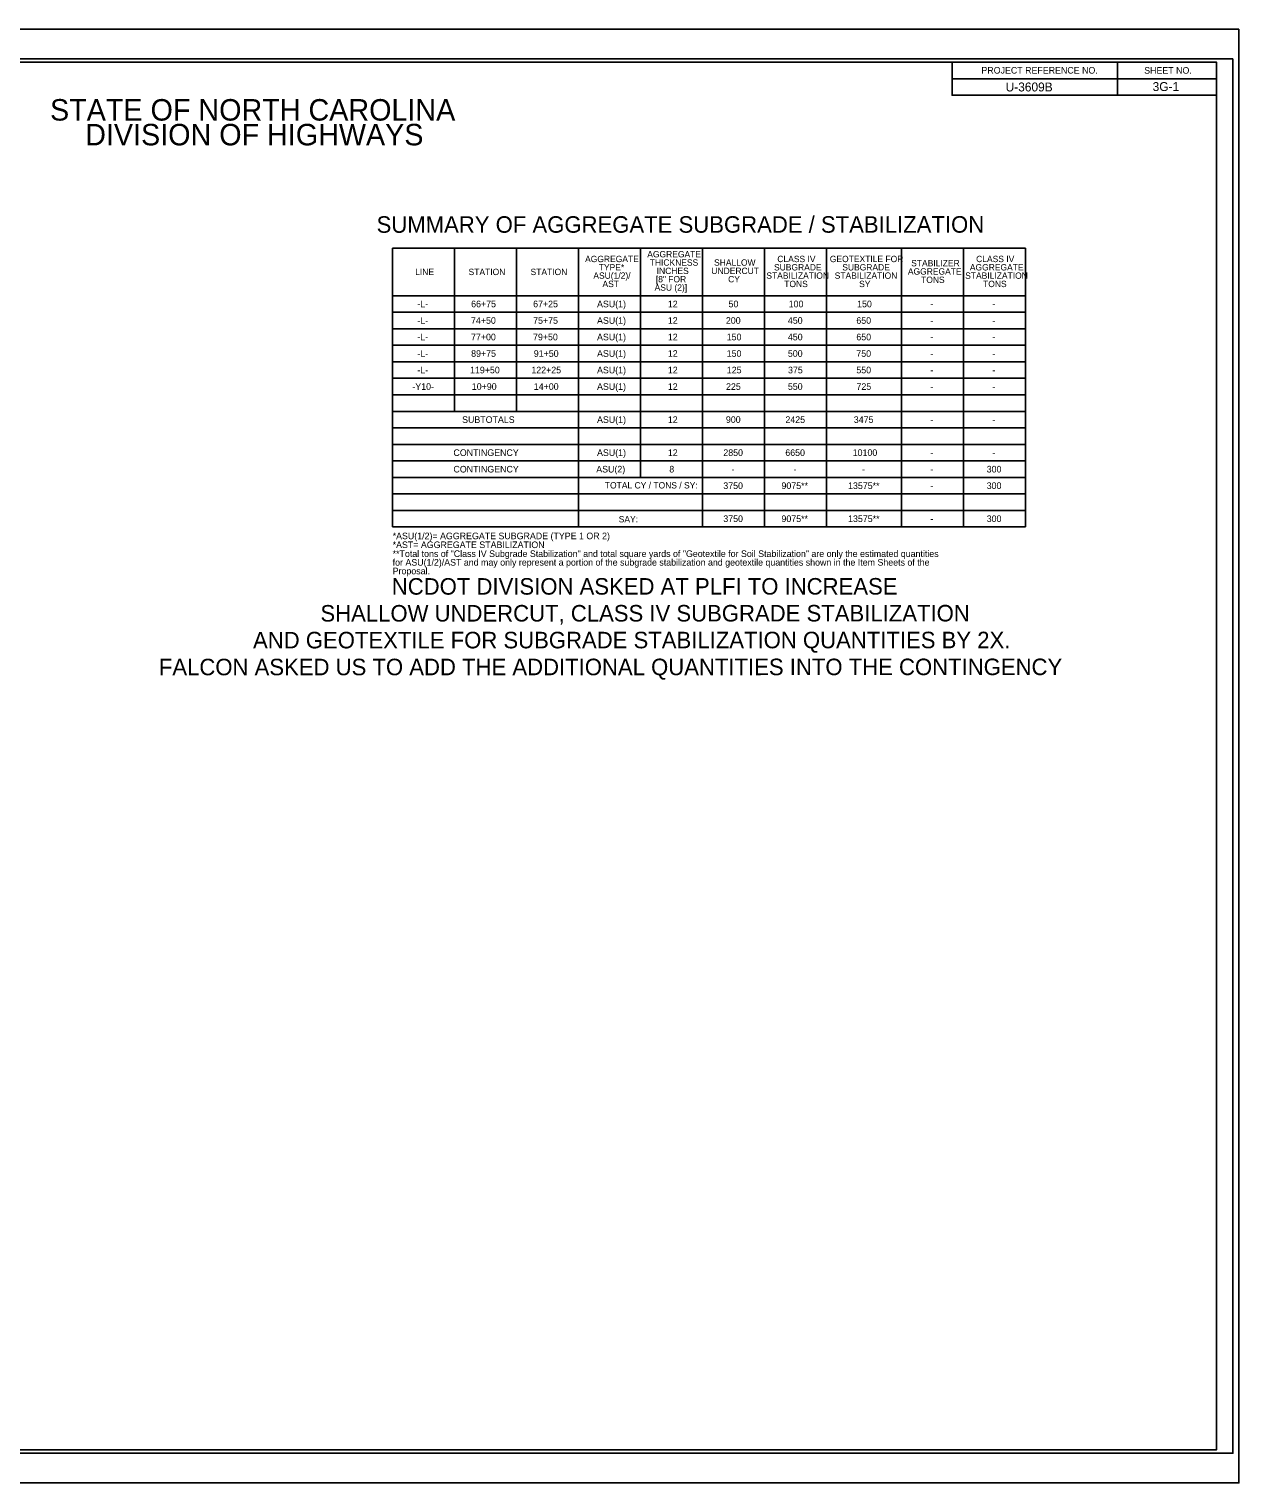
# Model space of a CAD drawing. Extents: x 1729992.2 to 1730025.9, y 539934.2 to 539956.2.
# Drawn here: x 1730007.57 to 1730025.88, y 539934.17 to 539956.17 of the extents above; entities that cross this region are included whole.
import ezdxf

# ---------------------------------------------------------------- set-up
doc = ezdxf.new("R2010")
doc.units = 0
for name, color, linetype in [('Scratch_Level_1', 7, 'Continuous'), ('Sheet Cutting Line CELL', 7, 'Continuous'), ('Sheet Data Field CELL', 7, 'Continuous'), ('Sheet Plot Border Inside CELL', 7, 'Continuous'), ('Sheet Plot Border Outside CELL', 7, 'Continuous'), ('Sheet Summary Combination CELL', 7, 'Continuous'), ('Sheet Summary Combination Grid CELL', 7, 'Continuous')]:
    doc.layers.add(name, color=color, linetype=linetype)

msp = doc.modelspace()

# ---------------------------------------------------------------- linework, layer by layer
at = {"layer": 'Sheet Cutting Line CELL'}
for p, q in [((1730025.883, 539956.171), (1729992.203, 539956.171)), ((1729992.203, 539934.171), (1730025.883, 539934.171))]:
    msp.add_line(p, q, dxfattribs=at)
at = {"layer": 'Sheet Plot Border Inside CELL'}
msp.add_lwpolyline([(1730025.793, 539955.722), (1729992.463, 539955.722), (1729992.463, 539934.62), (1730025.793, 539934.62)], close=True, dxfattribs=at)
at = {"layer": 'Sheet Plot Border Outside CELL'}
msp.add_lwpolyline([(1730025.883, 539956.171), (1729992.203, 539956.171), (1729992.203, 539934.171), (1730025.883, 539934.171)], close=True, dxfattribs=at)
at = {"layer": 'Sheet Summary Combination CELL'}
for p, q in [((1730024.043, 539955.67), (1730024.043, 539955.17)), ((1730021.542, 539955.42), (1730025.543, 539955.42)), ((1730021.542, 539955.17), (1730025.543, 539955.17)), ((1730015.901, 539952.635), (1730015.901, 539952.635)), ((1730016.026, 539952.633), (1730016.026, 539952.633)), ((1730016.207, 539952.637), (1730016.207, 539952.637)), ((1730016.319, 539952.635), (1730016.319, 539952.635))]:
    msp.add_line(p, q, dxfattribs=at)
for points in [[(1730025.543, 539955.671), (1729995.543, 539955.671), (1729995.543, 539934.671), (1730025.543, 539934.671)], [(1730021.542, 539955.671), (1730025.543, 539955.671), (1730025.543, 539955.17), (1730021.542, 539955.17)]]:
    msp.add_lwpolyline(points, close=True, dxfattribs=at)
at = {"layer": 'Sheet Summary Combination Grid CELL'}
for p, q in [((1730013.076, 539952.855), (1730022.651, 539952.855)), ((1730013.076, 539952.855), (1730013.076, 539948.636)), ((1730014.014, 539952.855), (1730014.014, 539950.386)), ((1730014.952, 539952.855), (1730014.952, 539950.386)), ((1730015.89, 539952.855), (1730015.89, 539948.636)), ((1730016.828, 539952.855), (1730016.828, 539949.386)), ((1730017.766, 539952.855), (1730017.766, 539948.636)), ((1730018.704, 539952.855), (1730018.704, 539948.636)), ((1730019.642, 539952.855), (1730019.642, 539948.636)), ((1730020.775, 539952.855), (1730020.775, 539948.636)), ((1730021.713, 539952.855), (1730021.713, 539948.636)), ((1730022.651, 539952.855), (1730022.651, 539948.636)), ((1730013.076, 539952.136), (1730022.651, 539952.136)), ((1730013.076, 539951.886), (1730022.651, 539951.886)), ((1730013.076, 539951.636), (1730022.651, 539951.636)), ((1730013.076, 539951.386), (1730022.651, 539951.386)), ((1730013.076, 539951.136), (1730022.651, 539951.136)), ((1730013.076, 539950.886), (1730022.651, 539950.886)), ((1730013.076, 539950.636), (1730022.651, 539950.636)), ((1730013.076, 539950.386), (1730022.651, 539950.386)), ((1730013.076, 539950.136), (1730022.651, 539950.136)), ((1730013.076, 539949.886), (1730022.651, 539949.886)), ((1730013.076, 539949.636), (1730022.651, 539949.636)), ((1730013.076, 539949.386), (1730022.651, 539949.386)), ((1730013.076, 539949.136), (1730022.651, 539949.136)), ((1730013.076, 539948.886), (1730022.651, 539948.886)), ((1730013.076, 539948.636), (1730022.651, 539948.636))]:
    msp.add_line(p, q, dxfattribs=at)

# ---------------------------------------------------------------- texts
at = {"layer": 'Scratch_Level_1'}
for s, p in [('NCDOT DIVISION ASKED AT PLFI TO INCREASE', (1730013.063, 539947.612)), ('SHALLOW UNDERCUT, CLASS IV SUBGRADE STABILIZATION', (1730011.983, 539947.205)), ('AND GEOTEXTILE FOR SUBGRADE STABILIZATION QUANTITIES BY 2X.', (1730010.963, 539946.799)), ('FALCON ASKED US TO ADD THE ADDITIONAL QUANTITIES INTO THE CONTINGENCY', (1730009.538, 539946.392))]:
    msp.add_text(s, height=0.25, rotation=0.0119, dxfattribs=at).set_placement(p)
at = {"layer": 'Sheet Data Field CELL'}
for s, p in [('U-3609B', (1730022.352, 539955.227)), ('3G-1', (1730024.577, 539955.233))]:
    msp.add_text(s, height=0.135, dxfattribs=at).set_placement(p)
at = {"layer": 'Sheet Summary Combination CELL'}
for s, height, p in [('PROJECT REFERENCE NO.', 0.1, (1730021.986, 539955.497)), ('SHEET NO.', 0.1, (1730024.449, 539955.495)), ('STATE OF NORTH CAROLINA', 0.325, (1730007.891, 539954.786)), ('DIVISION OF HIGHWAYS', 0.325, (1730008.423, 539954.411)), ('AGGREGATE', 0.096, (1730015.988, 539952.644)), ('TYPE*', 0.096, (1730016.195, 539952.518)), ('AGGREGATE', 0.096, (1730016.929, 539952.716)), ('THICKNESS', 0.096, (1730016.966, 539952.59)), ('SHALLOW', 0.096, (1730017.94, 539952.59)), ('SUBGRADE', 0.096, (1730018.847, 539952.518)), ('CLASS IV', 0.096, (1730018.897, 539952.644)), ('GEOTEXTILE FOR', 0.096, (1730019.692, 539952.644)), ('SUBGRADE', 0.096, (1730019.88, 539952.518)), ('STABILIZER', 0.096, (1730020.923, 539952.581)), ('AGGREGATE', 0.096, (1730021.811, 539952.518)), ('CLASS IV', 0.096, (1730021.906, 539952.644)), ('LINE', 0.096, (1730013.417, 539952.448)), ('STATION', 0.096, (1730014.225, 539952.448)), ('STATION', 0.096, (1730015.163, 539952.448)), ('ASU(1/2)/', 0.096, (1730016.113, 539952.392)), ('[8" FOR', 0.096, (1730017.059, 539952.338)), ('INCHES', 0.096, (1730017.072, 539952.464)), ('UNDERCUT', 0.096, (1730017.899, 539952.464)), ('CY', 0.096, (1730018.153, 539952.338)), ('STABILIZATION', 0.096, (1730018.731, 539952.392)), ('STABILIZATION', 0.096, (1730019.765, 539952.392)), ('AGGREGATE', 0.096, (1730020.873, 539952.455)), ('TONS', 0.096, (1730021.073, 539952.329)), ('STABILIZATION', 0.096, (1730021.74, 539952.392)), ('AST', 0.096, (1730016.251, 539952.266)), ('ASU (2)]', 0.096, (1730017.04, 539952.212)), ('TONS', 0.096, (1730019.002, 539952.266)), ('SY', 0.096, (1730020.135, 539952.266)), ('TONS', 0.096, (1730022.011, 539952.266)), ('-L-', 0.1, (1730013.449, 539951.961)), ('66+75', 0.1, (1730014.264, 539951.961)), ('67+25', 0.1, (1730015.202, 539951.961)), ('ASU(1)', 0.1, (1730016.169, 539951.961)), ('12', 0.1, (1730017.241, 539951.961)), ('50', 0.1, (1730018.159, 539951.961)), ('100', 0.1, (1730019.069, 539951.961)), ('150', 0.1, (1730020.105, 539951.961)), ('-', 0.1, (1730021.214, 539951.961)), ('-', 0.1, (1730022.152, 539951.961)), ('-L-', 0.1, (1730013.449, 539951.711)), ('74+50', 0.1, (1730014.262, 539951.711)), ('75+75', 0.1, (1730015.202, 539951.711)), ('ASU(1)', 0.1, (1730016.169, 539951.711)), ('12', 0.1, (1730017.241, 539951.711)), ('200', 0.1, (1730018.119, 539951.711)), ('450', 0.1, (1730019.057, 539951.711)), ('650', 0.1, (1730020.093, 539951.711)), ('-', 0.1, (1730021.214, 539951.711)), ('-', 0.1, (1730022.152, 539951.711)), ('-L-', 0.1, (1730013.449, 539951.461)), ('77+00', 0.1, (1730014.262, 539951.461)), ('79+50', 0.1, (1730015.2, 539951.461)), ('ASU(1)', 0.1, (1730016.169, 539951.461)), ('12', 0.1, (1730017.241, 539951.461)), ('150', 0.1, (1730018.131, 539951.461)), ('450', 0.1, (1730019.057, 539951.461)), ('650', 0.1, (1730020.093, 539951.461)), ('-', 0.1, (1730021.214, 539951.461)), ('-', 0.1, (1730022.152, 539951.461)), ('-L-', 0.1, (1730013.449, 539951.211)), ('89+75', 0.1, (1730014.264, 539951.211)), ('91+50', 0.1, (1730015.212, 539951.211)), ('ASU(1)', 0.1, (1730016.169, 539951.211)), ('12', 0.1, (1730017.241, 539951.211)), ('150', 0.1, (1730018.131, 539951.211)), ('500', 0.1, (1730019.057, 539951.211)), ('750', 0.1, (1730020.093, 539951.211)), ('-L-', 0.1, (1730013.449, 539950.961)), ('119+50', 0.1, (1730014.247, 539950.961)), ('122+25', 0.1, (1730015.175, 539950.961)), ('ASU(1)', 0.1, (1730016.169, 539950.961)), ('12', 0.1, (1730017.241, 539950.961)), ('125', 0.1, (1730018.133, 539950.961)), ('375', 0.1, (1730019.059, 539950.961)), ('550', 0.1, (1730020.093, 539950.961)), ('-', 0.1, (1730021.214, 539951.211)), ('-', 0.1, (1730022.152, 539951.211)), ('-', 0.1, (1730021.214, 539950.961)), ('-', 0.1, (1730022.152, 539950.961)), ('-Y10-', 0.1, (1730013.374, 539950.711)), ('10+90', 0.1, (1730014.274, 539950.711)), ('14+00', 0.1, (1730015.212, 539950.711)), ('ASU(1)', 0.1, (1730016.169, 539950.711)), ('12', 0.1, (1730017.241, 539950.711)), ('225', 0.1, (1730018.121, 539950.711)), ('550', 0.1, (1730019.057, 539950.711)), ('725', 0.1, (1730020.095, 539950.711)), ('-', 0.1, (1730021.214, 539950.711)), ('-', 0.1, (1730022.152, 539950.711)), ('SUBTOTALS', 0.1, (1730014.127, 539950.211)), ('ASU(1)', 0.1, (1730016.169, 539950.211)), ('12', 0.1, (1730017.241, 539950.211)), ('900', 0.1, (1730018.119, 539950.211)), ('2425', 0.1, (1730019.02, 539950.211)), ('3475', 0.1, (1730020.055, 539950.211)), ('-', 0.1, (1730021.214, 539950.211)), ('-', 0.1, (1730022.152, 539950.211)), ('CONTINGENCY', 0.1, (1730013.996, 539949.711)), ('ASU(1)', 0.1, (1730016.169, 539949.711)), ('12', 0.1, (1730017.241, 539949.711)), ('2850', 0.1, (1730018.08, 539949.711)), ('6650', 0.1, (1730019.018, 539949.711)), ('10100', 0.1, (1730020.038, 539949.711)), ('-', 0.1, (1730021.214, 539949.711)), ('-', 0.1, (1730022.152, 539949.711)), ('CONTINGENCY', 0.1, (1730013.996, 539949.461)), ('ASU(2)', 0.1, (1730016.157, 539949.461)), ('8', 0.1, (1730017.263, 539949.461)), ('300', 0.1, (1730022.066, 539949.461)), ('TOTAL CY / TONS / SY:', 0.096, (1730016.287, 539949.219)), ('3750', 0.1, (1730018.08, 539949.211)), ('-', 0.1, (1730018.205, 539949.461)), ('9075**', 0.1, (1730018.96, 539949.211)), ('-', 0.1, (1730019.143, 539949.461)), ('13575**', 0.1, (1730019.968, 539949.211)), ('-', 0.1, (1730020.179, 539949.461)), ('-', 0.1, (1730021.214, 539949.461)), ('300', 0.1, (1730022.066, 539949.211)), ('-', 0.1, (1730021.214, 539949.211)), ('SAY:', 0.096, (1730016.497, 539948.706)), ('3750', 0.1, (1730018.08, 539948.711)), ('9075**', 0.1, (1730018.96, 539948.711)), ('13575**', 0.1, (1730019.968, 539948.711)), ('-', 0.1, (1730021.214, 539948.711)), ('300', 0.1, (1730022.066, 539948.711)), ('*ASU(1/2)= AGGREGATE SUBGRADE (TYPE 1 OR 2)', 0.1, (1730013.076, 539948.451)), ('*AST= AGGREGATE STABILIZATION', 0.1, (1730013.076, 539948.317)), ('**Total tons of "Class IV Subgrade Stabilization" and total square yards of "Geotextile for Soil Stabilization" are only the estimated quantities', 0.1, (1730013.076, 539948.182)), ('for ASU(1/2)/AST and may only represent a portion of the subgrade stabilization and geotextile quantities shown in the Item Sheets of the', 0.1, (1730013.076, 539948.051)), ('Proposal.', 0.1, (1730013.076, 539947.92))]:
    msp.add_text(s, height=height, dxfattribs=at).set_placement(p)
msp.add_text('SUMMARY OF AGGREGATE SUBGRADE / STABILIZATION', height=0.25, rotation=0.0119, dxfattribs=at).set_placement((1730012.833, 539953.088))

doc.saveas('drawing.dxf')
